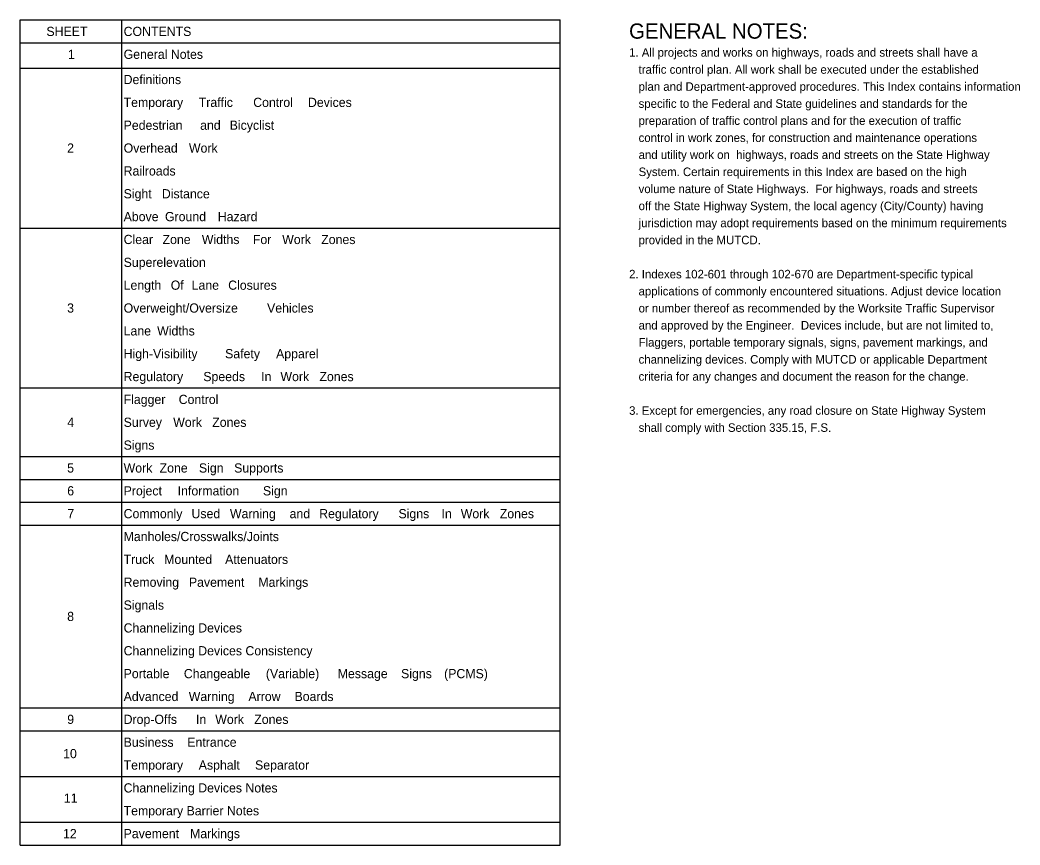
# Model space of a CAD drawing. Extents: x 10182 to 10593, y 10112 to 10451.
import ezdxf

# ---------------------------------------------------------------- set-up
doc = ezdxf.new("R2010")
doc.units = 0
doc.layers.add('SumBoxLines_dp', color=7, linetype='Continuous')
doc.layers.add('SupstrConc', color=7, linetype='Continuous')

msp = doc.modelspace()

# ---------------------------------------------------------------- linework, layer by layer
at = {"layer": 'SumBoxLines_dp'}
for p, q in [((10182.32, 10112.08), (10182.32, 10450.75)), ((10182.32, 10450.75), (10404.09, 10450.75)), ((10224.19, 10112.08), (10224.19, 10450.75)), ((10404.09, 10112.08), (10404.09, 10450.75)), ((10182.32, 10441.37), (10404.09, 10441.37)), ((10182.32, 10431.01), (10404.09, 10431.01)), ((10182.32, 10365.35), (10404.09, 10365.35)), ((10182.32, 10299.69), (10404.09, 10299.69)), ((10182.32, 10271.55), (10404.09, 10271.55)), ((10182.32, 10262.17), (10404.09, 10262.17)), ((10182.32, 10252.79), (10404.09, 10252.79)), ((10182.32, 10243.41), (10404.09, 10243.41)), ((10182.32, 10168.36), (10404.09, 10168.36)), ((10182.32, 10158.98), (10404.09, 10158.98)), ((10182.32, 10140.22), (10404.09, 10140.22)), ((10182.32, 10121.46), (10404.09, 10121.46)), ((10182.32, 10112.08), (10404.09, 10112.08))]:
    msp.add_line(p, q, dxfattribs=at)

# ---------------------------------------------------------------- texts
at = {"layer": 'SupstrConc'}
for s, height, p in [('GENERAL NOTES:', 6.25, (10432.37, 10443.08)), ('SHEET', 3.78, (10193.16, 10444.17)), ('CONTENTS', 3.78, (10224.86, 10444.17)), ('1', 3.78, (10202.01, 10434.79)), ('General Notes', 3.7796, (10224.86, 10434.79)), ('1. All projects and works on highways, roads and streets shall have a', 3.5, (10432.37, 10435.68)), ('   traffic control plan. All work shall be executed under the established', 3.5, (10432.37, 10428.68)), ('Definitions', 3.7796, (10224.86, 10424.43)), ('   plan and Department-approved procedures. This Index contains information', 3.5, (10432.37, 10421.68)), ('Temporary', 3.78, (10224.86, 10415.05)), (' Traffic', 3.78, (10254.28, 10415.05)), (' Control', 3.78, (10276.65, 10415.05)), (' Devices', 3.78, (10299.13, 10415.05)), ('   specific to the Federal and State guidelines and standards for the', 3.5, (10432.37, 10414.68)), ('   preparation of traffic control plans and for the execution of traffic', 3.5, (10432.37, 10407.68)), ('Pedestrian', 3.78, (10224.86, 10405.67)), (' and', 3.78, (10254.86, 10405.67)), (' Bicyclist', 3.78, (10267, 10405.67)), ('   control in work zones, for construction and maintenance operations', 3.5, (10432.37, 10400.68)), ('2', 3.78, (10201.67, 10396.29)), ('Overhead', 3.78, (10224.86, 10396.29)), (' Work', 3.78, (10250.27, 10396.29)), ('   and utility work on  highways, roads and streets on the State Highway', 3.5, (10432.37, 10393.68)), ('Railroads', 3.78, (10224.86, 10386.91)), ('   System. Certain requirements in this Index are based on the high ', 3.5, (10432.37, 10386.68)), ('   volume nature of State Highways.  For highways, roads and streets ', 3.5, (10432.37, 10379.68)), ('Sight', 3.78, (10224.86, 10377.53)), (' Distance', 3.78, (10239.15, 10377.53)), ('   off the State Highway System, the local agency (City/County) having ', 3.5, (10432.37, 10372.68)), ('Above', 3.78, (10224.86, 10368.15)), (' Ground', 3.78, (10240.43, 10368.15)), (' Hazard', 3.78, (10262.1, 10368.15)), ('   jurisdiction may adopt requirements based on the minimum requirements ', 3.5, (10432.37, 10365.68)), ('Clear', 3.78, (10224.86, 10358.77)), (' Zone', 3.78, (10239.43, 10358.77)), (' Widths', 3.78, (10255.56, 10358.77)), (' For', 3.78, (10276.51, 10358.77)), (' Work', 3.78, (10288.55, 10358.77)), (' Zones', 3.78, (10304.57, 10358.77)), ('   provided in the MUTCD.', 3.5, (10432.37, 10358.68)), ('Superelevation', 3.7796, (10224.86, 10349.39)), ('2. Indexes 102-601 through 102-670 are Department-specific typical ', 3.5, (10432.37, 10344.68)), ('Length', 3.78, (10224.86, 10340.01)), (' Of', 3.78, (10242.79, 10340.01)), (' Lane', 3.78, (10251.38, 10340.01)), (' Closures', 3.78, (10266.38, 10340.01)), ('   applications of commonly encountered situations. Adjust device location ', 3.5, (10432.37, 10337.68)), ('3', 3.78, (10201.67, 10330.63)), ('Overweight/Oversize', 3.7796, (10224.86, 10330.63)), (' Vehicles', 3.78, (10282.34, 10330.63)), ('   or number thereof as recommended by the Worksite Traffic Supervisor ', 3.5, (10432.37, 10330.68)), ('Lane', 3.78, (10224.86, 10321.25)), (' Widths', 3.78, (10237.21, 10321.25)), ('   and approved by the Engineer.  Devices include, but are not limited to, ', 3.5, (10432.37, 10323.68)), ('   Flaggers, portable temporary signals, signs, pavement markings, and ', 3.5, (10432.37, 10316.68)), ('High-Visibility', 3.7796, (10224.86, 10311.87)), (' Safety', 3.78, (10265.11, 10311.87)), (' Apparel', 3.78, (10286.04, 10311.87)), ('   channelizing devices. Comply with MUTCD or applicable Department ', 3.5, (10432.37, 10309.68)), ('Regulatory', 3.78, (10224.86, 10302.49)), ('  Speeds', 3.78, (10254.76, 10302.49)), (' In', 3.78, (10279.93, 10302.49)), (' Work', 3.78, (10287.83, 10302.49)), (' Zones', 3.78, (10303.84, 10302.49)), ('   criteria for any changes and document the reason for the change. ', 3.5, (10432.37, 10302.68)), ('Flagger', 3.78, (10224.86, 10293.11)), (' Control', 3.78, (10246.06, 10293.11)), ('3. Except for emergencies, any road closure on State Highway System ', 3.5, (10432.37, 10288.68)), ('4', 3.78, (10201.74, 10283.73)), ('Survey', 3.78, (10224.86, 10283.73)), (' Work', 3.78, (10243.81, 10283.73)), (' Zones', 3.78, (10259.83, 10283.73)), ('   shall comply with Section 335.15, F.S.', 3.5, (10432.37, 10281.68)), ('Signs', 3.78, (10224.86, 10274.35)), ('5', 3.78, (10201.69, 10264.97)), ('Work', 3.78, (10224.86, 10264.97)), (' Zone', 3.78, (10238.23, 10264.97)), (' Sign', 3.78, (10254.36, 10264.97)), (' Supports', 3.78, (10268.82, 10264.97)), ('6', 3.78, (10201.71, 10255.59)), ('Project', 3.78, (10224.86, 10255.59)), (' Information', 3.7796, (10245.65, 10255.59)), (' Sign', 3.78, (10280.65, 10255.59)), ('7', 3.78, (10201.76, 10246.21)), ('Commonly', 3.78, (10224.86, 10246.21)), (' Used', 3.78, (10251.32, 10246.21)), (' Warning', 3.78, (10267.1, 10246.21)), (' and', 3.78, (10291.59, 10246.21)), (' Regulatory', 3.7796, (10303.73, 10246.21)), (' Signs', 3.78, (10336.28, 10246.21)), (' In', 3.78, (10353.96, 10246.21)), (' Work', 3.78, (10361.86, 10246.21)), (' Zones', 3.78, (10377.88, 10246.21)), ('Manholes/Crosswalks/Joints', 3.7796, (10224.86, 10236.83)), ('Truck', 3.78, (10224.86, 10227.45)), (' Mounted', 3.78, (10240.11, 10227.45)), (' Attenuators', 3.7796, (10265.12, 10227.45)), ('Removing', 3.78, (10224.86, 10218.07)), (' Pavement', 3.78, (10250.25, 10218.07)), (' Markings', 3.78, (10278.76, 10218.07)), ('Signals', 3.78, (10224.86, 10208.69)), ('8', 3.78, (10201.68, 10204.02)), ('Channelizing Devices', 3.7796, (10224.86, 10199.31)), ('Channelizing Devices Consistency', 3.7796, (10224.86, 10189.93)), ('Portable', 3.78, (10224.86, 10180.55)), (' Changeable', 3.7796, (10248.17, 10180.55)), (' (Variable)', 3.7796, (10281.85, 10180.55)), (' Message', 3.78, (10311.34, 10180.55)), (' Signs', 3.78, (10337.35, 10180.55)), (' (PCMS)', 3.78, (10355.02, 10180.55)), ('Advanced', 3.78, (10224.86, 10171.17)), (' Warning', 3.78, (10250.19, 10171.17)), (' Arrow', 3.78, (10274.68, 10171.17)), (' Boards', 3.78, (10293.61, 10171.17)), ('9', 3.78, (10201.71, 10161.78)), ('Drop-Offs', 3.78, (10224.86, 10161.78)), (' In', 3.78, (10253.17, 10161.78)), (' Work', 3.78, (10261.07, 10161.78)), (' Zones', 3.78, (10277.08, 10161.78)), ('Business', 3.78, (10224.86, 10152.4)), (' Entrance', 3.78, (10249.59, 10152.4)), ('10', 3.78, (10200.02, 10147.71)), ('Temporary', 3.78, (10224.86, 10143.02)), (' Asphalt', 3.78, (10254.28, 10143.02)), (' Separator', 3.78, (10277.41, 10143.02)), ('Channelizing Devices Notes', 3.7796, (10224.86, 10133.64)), ('11', 3.78, (10200.31, 10129.42)), ('Temporary Barrier Notes', 3.7796, (10224.86, 10124.26)), ('12', 3.78, (10199.97, 10114.88)), ('Pavement', 3.78, (10224.86, 10114.88)), (' Markings', 3.78, (10250.72, 10114.88))]:
    msp.add_text(s, height=height, dxfattribs=at).set_placement(p)

doc.saveas('drawing.dxf')
